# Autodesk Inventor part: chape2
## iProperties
Created: 2009-03
Part Number: chape2
Document SubType Name: Modeling
Designer: Ordi1
Author: Ordi1
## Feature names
1. Extrusion1
2. Perçage1 [Hole]
3. Chanfrein1 [Chamfer]
